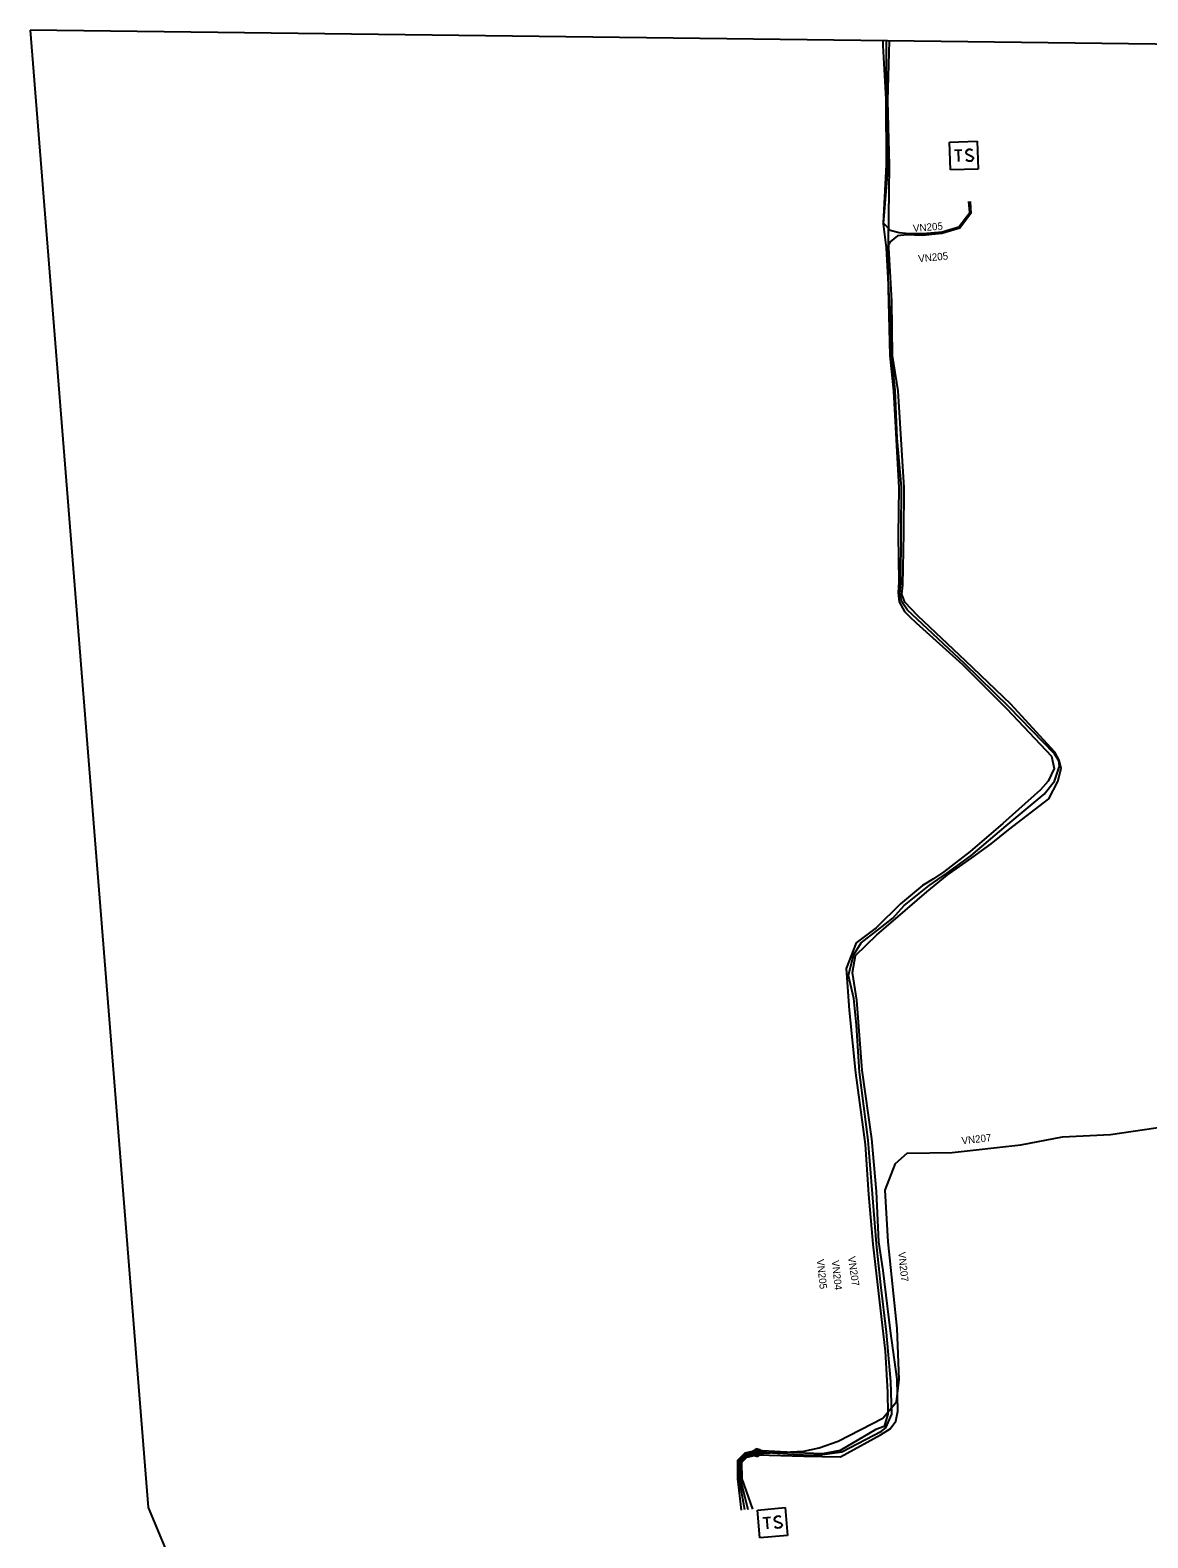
# Model space of a CAD drawing. Extents: x -641829 to -641525, y -1114855 to -1114359.
# Drawn here: x -641828.7 to -641677, y -1114563.5 to -1114358.9 of the extents above; entities that cross this region are included whole.
import ezdxf

# ---------------------------------------------------------------- set-up
doc = ezdxf.new("R2010")
doc.units = 0
for name, color, linetype in [('19', 7, 'Continuous'), ('25', 7, 'Continuous'), ('5', 7, 'Continuous'), ('7', 7, 'Continuous'), ('Vrstva 1', 7, 'Continuous')]:
    doc.layers.add(name, color=color, linetype=linetype)

# ---------------------------------------------------------------- blocks, each defined once
blk = doc.blocks.new('VN870')
at = {"layer": '19'}
for points in [[(0, -0.25), (0.5, 0), (0, 0.25), (-0.5, 0), (0, -0.25)], [(0.37, 0), (0, 0.19), (-0.36, 0), (0, -0.19), (0.37, 0)], [(0.24, 0), (0, 0.12), (-0.25, 0), (0, -0.12), (0.24, 0)], [(0.12, 0), (0, 0.06), (-0.13, 0), (0, -0.06), (0.12, 0)]]:
    blk.add_lwpolyline(points, dxfattribs=at)
blk = doc.blocks.new('VN640')
at = {"layer": '25'}
for points in [[(-1.89, 1.89), (1.89, 1.89)], [(-1.89, -1.89), (-1.89, 1.89)], [(-1.26, 0.79), (-0.22, 0.79)], [(-0.73, 0.79), (-0.73, -0.79)], [(1.2, 0.66), (0.94, 0.79), (0.66, 0.79), (0.41, 0.66), (0.28, 0.47), (0.28, 0.41), (0.41, 0.22), (1.13, -0.16), (1.26, -0.32), (1.26, -0.47), (1.13, -0.66), (0.91, -0.79), (0.63, -0.79), (0.5, -0.73), (0.28, -0.6)], [(1.89, 1.89), (1.89, -1.89)], [(1.89, -1.89), (-1.89, -1.89)]]:
    blk.add_lwpolyline(points, dxfattribs=at)

msp = doc.modelspace()

# ---------------------------------------------------------------- linework, layer by layer
at = {"layer": '5'}
for points in [[(-641730.05, -1114551.82), (-641723.72, -1114552.21), (-641721.75, -1114552.28), (-641718.5, -1114551.83), (-641713.11, -1114549), (-641712.54, -1114548.55), (-641711.72, -1114546.7), (-641711.86, -1114542.28), (-641712.44, -1114535.56), (-641713.24, -1114529.13), (-641713.81, -1114523.58), (-641714.35, -1114516.8), (-641714.93, -1114509.54), (-641716.13, -1114500.3), (-641716.51, -1114493.92), (-641716.9, -1114490.3), (-641717.62, -1114487.16), (-641716.95, -1114484.42), (-641715.88, -1114482.73), (-641713.69, -1114481.03), (-641711.6, -1114479.38), (-641710.04, -1114477.68), (-641706.65, -1114474.97), (-641704.32, -1114473.35), (-641701.03, -1114470.92), (-641696.23, -1114466.85), (-641691.05, -1114462.56), (-641689.67, -1114460.8), (-641688.99, -1114458.78), (-641689.06, -1114458.06), (-641689.67, -1114457.09), (-641695.8, -1114450.77), (-641701.85, -1114444.83), (-641708.28, -1114438.8), (-641709.6, -1114437.61), (-641710.38, -1114436.46), (-641710.63, -1114435.36), (-641710.53, -1114433.95), (-641710.47, -1114426.96), (-641710.44, -1114420.91), (-641711.02, -1114414.25), (-641711.26, -1114407.73), (-641711.72, -1114403.2), (-641712.05, -1114395.79), (-641712.46, -1114388.43), (-641712.85, -1114385.19), (-641712.21, -1114377.42), (-641712.42, -1114368.39), (-641712.47, -1114361.12), (-641712.45, -1114360.33)], [(-641729.97, -1114552.21), (-641723.66, -1114552.4), (-641718.69, -1114552.49), (-641713.29, -1114549.52), (-641711.94, -1114548.68), (-641711.2, -1114547.65), (-641710.93, -1114546.28), (-641711.01, -1114541.97), (-641711.89, -1114535.37), (-641712.92, -1114527.19), (-641713.49, -1114523.3), (-641713.8, -1114516.48), (-641714.46, -1114509.33), (-641715.77, -1114500.04), (-641716.49, -1114490.53), (-641717.08, -1114486.77), (-641716.66, -1114484.45), (-641713.76, -1114481.64), (-641711.24, -1114479.48), (-641707, -1114475.81), (-641704.24, -1114473.54), (-641700.87, -1114471.19), (-641698.25, -1114469.3), (-641695.88, -1114467.42), (-641690.4, -1114463.22), (-641689.22, -1114460.85), (-641688.76, -1114459.09), (-641689.03, -1114457.94), (-641689.61, -1114456.87), (-641695.58, -1114450.35), (-641701.74, -1114444.45), (-641708.22, -1114438.35), (-641709.98, -1114436.49), (-641710.35, -1114435.42), (-641710.25, -1114434.22), (-641710.09, -1114427.13), (-641710.07, -1114420.98), (-641710.89, -1114407.82), (-641711.64, -1114403.03), (-641711.73, -1114395.68), (-641712.2, -1114387.6), (-641712.06, -1114377.27), (-641712.28, -1114368.46), (-641712.06, -1114360.33)], [(-641712.93, -1114360.32), (-641712.96, -1114360.97), (-641712.55, -1114368.29), (-641712.52, -1114377.18), (-641712.89, -1114385.04), (-641711.96, -1114386.04), (-641710.73, -1114386.35), (-641709.38, -1114386.5), (-641707.47, -1114386.5), (-641704.88, -1114386.28), (-641702.63, -1114385.59), (-641701.14, -1114383.63), (-641701.26, -1114382.16)], [(-641701.08, -1114382.15), (-641700.99, -1114383.75), (-641702.52, -1114385.77), (-641704.95, -1114386.49), (-641707.62, -1114386.75), (-641709.68, -1114386.65), (-641710.96, -1114386.78), (-641711.94, -1114387.6), (-641712.37, -1114388.34), (-641712.19, -1114395.74), (-641711.99, -1114403.02), (-641711.51, -1114407.86), (-641710.76, -1114421), (-641710.85, -1114427.43), (-641710.78, -1114433.74), (-641710.88, -1114435.26), (-641710.73, -1114436.47), (-641709.99, -1114437.78), (-641709.27, -1114438.5), (-641708.44, -1114439.32), (-641702.14, -1114444.98), (-641696.1, -1114451), (-641690.08, -1114457.39), (-641689.7, -1114459.08), (-641690.51, -1114460.79), (-641691.56, -1114461.96), (-641696.65, -1114466.54), (-641701.09, -1114470.33), (-641704.65, -1114473.11), (-641706.08, -1114474.06), (-641707.55, -1114474.94), (-641710.55, -1114477.44), (-641713.85, -1114480.72), (-641716.56, -1114482.74), (-641717.93, -1114486.23), (-641717.51, -1114491.87), (-641716.68, -1114500.39), (-641715.36, -1114510.12), (-641714.9, -1114516.9), (-641714.29, -1114523.62), (-641713.69, -1114529.17), (-641712.64, -1114538.13), (-641712.3, -1114543.73), (-641712.25, -1114546.72), (-641712.77, -1114548.38), (-641713.89, -1114548.78), (-641718.73, -1114551.63), (-641721.15, -1114552.1), (-641723.55, -1114552.01), (-641730.09, -1114551.63)], [(-641730.01, -1114552.02), (-641723.69, -1114551.7), (-641721.58, -1114551.28), (-641718.99, -1114550.38), (-641712.95, -1114547.26), (-641711.08, -1114545.01), (-641710.72, -1114541.98), (-641710.99, -1114535.07), (-641712.22, -1114523.3), (-641712.63, -1114516.29), (-641711.24, -1114512.67), (-641709.67, -1114511.27), (-641703.54, -1114511.2), (-641694.21, -1114510.13), (-641688.55, -1114509.05), (-641682.04, -1114508.75), (-641668.53, -1114506.77)], [(-641730.09, -1114551.63), (-641731.69, -1114551.98), (-641732.67, -1114552.98), (-641732.66, -1114555.48), (-641732.17, -1114559.74)], [(-641731.68, -1114559.7), (-641732.46, -1114555.48), (-641732.47, -1114553.06), (-641731.59, -1114552.16), (-641730.05, -1114551.82)], [(-641731.23, -1114559.66), (-641732.26, -1114555.48), (-641732.27, -1114553.14), (-641731.49, -1114552.34), (-641730.01, -1114552.02)], [(-641730.58, -1114559.6), (-641732.06, -1114555.48), (-641732.07, -1114553.22), (-641731.39, -1114552.52), (-641729.97, -1114552.21)]]:
    msp.add_lwpolyline(points, dxfattribs=at)
at = {"layer": 'Vrstva 1'}
for p, q in [((-641525.3, -1114362.64), (-641828.67, -1114358.89)), ((-641828.67, -1114358.89), (-641812.64, -1114559.36)), ((-641812.64, -1114559.36), (-641689.21, -1114854.71))]:
    msp.add_line(p, q, dxfattribs=at)

# ---------------------------------------------------------------- block references
at = {"layer": '19', "rotation": 13}
for p in [(-641730.09, -1114551.63), (-641730.05, -1114551.82), (-641730.01, -1114552.02), (-641729.97, -1114552.21)]:
    msp.add_blockref('VN870', p, dxfattribs=at)
at = {"layer": '25'}
for p, rotation in [((-641701.96, -1114375.91), 2), ((-641727.93, -1114561.43), 5)]:
    msp.add_blockref('VN640', p, dxfattribs=dict(at, rotation=rotation))

# ---------------------------------------------------------------- texts
at = {"layer": '7'}
for s, rotation, p in [('VN205', 4.7819, (-641708.82, -1114386.28)), ('VN205', 5.5344, (-641708.1, -1114390.39)), ('VN207', 6.5414, (-641702.21, -1114510.1)), ('VN207', 275.9827, (-641710.87, -1114524.73)), ('VN205', 276.1567, (-641721.93, -1114525.73)), ('VN204', 275.8631, (-641719.88, -1114525.86)), ('VN207', 278.3074, (-641717.69, -1114525.36))]:
    msp.add_text(s, height=0.994, rotation=rotation, dxfattribs=at).set_placement(p)

doc.saveas('drawing.dxf')
